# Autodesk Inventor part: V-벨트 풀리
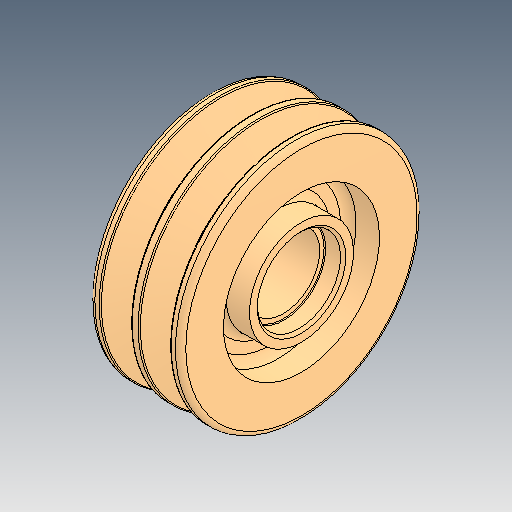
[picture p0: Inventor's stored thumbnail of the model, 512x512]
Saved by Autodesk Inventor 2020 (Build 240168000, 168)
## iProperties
Created: 2025-01
Part Number: V-벨트 풀리
Material: 강철, 주조
Document SubType Name: Modeling
Designer: 1강의실14
Density: 7.85 g/cm^3
Appearance: 기본값
Author: jhkim
Sending System: Autodesk Inventor 2025
Preprocessor: ST-DEVELOPER v20
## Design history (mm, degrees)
feature "솔리드1"
node "솔리드2"
